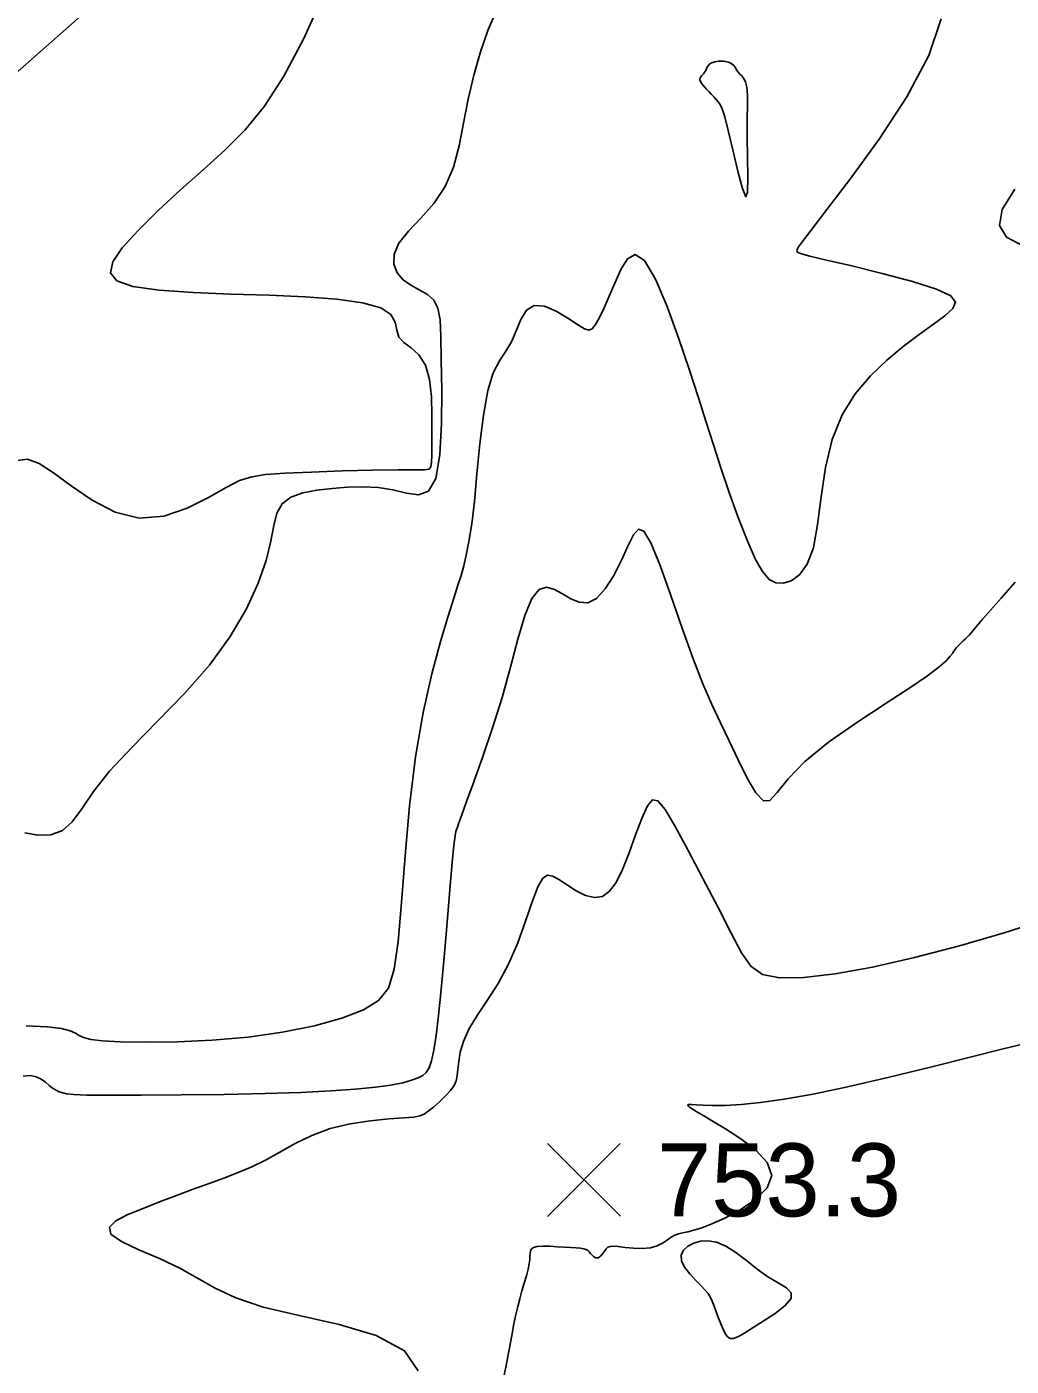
# Model space of a CAD drawing. Extents: x 2566142 to 2571431, y 418755 to 421584.
# Drawn here: x 2568243.6 to 2568445.9, y 420968.6 to 421243.9 of the extents above; entities that cross this region are included whole.
import ezdxf

# ---------------------------------------------------------------- set-up
doc = ezdxf.new("R2010")
doc.units = 0
for name, color, linetype in [('Contour_ADS_Major', 7, 'Continuous'), ('Contour_ADS_Minor', 7, 'Continuous'), ('Contour_ADS_Spot_Elevation', 7, 'Continuous')]:
    doc.layers.add(name, color=color, linetype=linetype)

# ---------------------------------------------------------------- blocks, each defined once
blk = doc.blocks.new('S750')
at = {"layer": 'Contour_ADS_Spot_Elevation'}
for p, q in [((-0.5, 0.498), (0.5, -0.498)), ((-0.498, -0.5), (0.498, 0.5))]:
    blk.add_line(p, q, dxfattribs=at)

msp = doc.modelspace()

# ---------------------------------------------------------------- linework, layer by layer
at = {"layer": 'Contour_ADS_Major'}
msp.add_lwpolyline([(2568243.2, 421078.22), (2568245.83, 421077.73), (2568248.5, 421077.82), (2568250.92, 421078.7), (2568252.94, 421080.51), (2568254.9, 421083.21), (2568257.29, 421086.71), (2568260.61, 421090.95), (2568265.15, 421095.81), (2568270.49, 421101.17), (2568276.04, 421106.85), (2568281.18, 421112.71), (2568285.42, 421118.57), (2568288.73, 421124.25), (2568291.17, 421129.54), (2568292.8, 421134.24), (2568293.75, 421138.2), (2568294.36, 421141.42), (2568295.01, 421143.96), (2568296.09, 421145.87), (2568297.9, 421147.22), (2568300.34, 421148.12), (2568303.21, 421148.68), (2568306.34, 421149.04), (2568309.54, 421149.27), (2568312.73, 421149.35), (2568315.85, 421149.2), (2568318.85, 421148.74), (2568321.64, 421148.05), (2568324.12, 421147.72), (2568326.16, 421148.48), (2568327.64, 421151.09), (2568328.49, 421155.96), (2568328.85, 421162.35), (2568328.89, 421169.2), (2568328.8, 421175.43), (2568328.72, 421180.23), (2568328.54, 421183.67), (2568328.11, 421186.05), (2568327.27, 421187.7), (2568325.94, 421188.89), (2568324.28, 421189.85), (2568322.53, 421190.79), (2568320.94, 421191.91), (2568319.72, 421193.36), (2568319.06, 421195.14), (2568319.12, 421197.19), (2568320.1, 421199.44), (2568322.03, 421201.88), (2568324.58, 421204.56), (2568327.26, 421207.58), (2568329.62, 421211.05), (2568331.29, 421215.02), (2568332.45, 421219.41), (2568333.35, 421224.11), (2568334.29, 421229.01), (2568335.46, 421233.98), (2568336.85, 421238.77), (2568338.37, 421243.13), (2568339.91, 421246.78)], dxfattribs=at)
msp.add_lwpolyline([(2568387.78, 421222.59), (2568388.71, 421218.59), (2568389.73, 421214.24), (2568390.68, 421210.66), (2568391.39, 421208.97), (2568391.75, 421209.94), (2568391.83, 421212.96), (2568391.76, 421217.07), (2568391.68, 421221.31), (2568391.68, 421224.89), (2568391.72, 421227.72), (2568391.72, 421229.9), (2568391.6, 421231.5), (2568391.32, 421232.62), (2568390.93, 421233.37), (2568390.49, 421233.88), (2568390.09, 421234.26), (2568389.77, 421234.63), (2568389.52, 421235), (2568389.31, 421235.34), (2568389.12, 421235.65), (2568388.9, 421235.91), (2568388.66, 421236.14), (2568388.4, 421236.33), (2568388.12, 421236.49), (2568387.82, 421236.62), (2568387.5, 421236.72), (2568387.17, 421236.79), (2568386.83, 421236.84), (2568386.5, 421236.86), (2568386.16, 421236.86), (2568385.8, 421236.83), (2568385.42, 421236.78), (2568385.01, 421236.69), (2568384.6, 421236.57), (2568384.21, 421236.39), (2568383.88, 421236.14), (2568383.61, 421235.82), (2568383.39, 421235.46), (2568383.21, 421235.08), (2568383.04, 421234.74), (2568382.86, 421234.46), (2568382.67, 421234.23), (2568382.48, 421234.02), (2568382.29, 421233.82), (2568382.12, 421233.6), (2568381.99, 421233.34), (2568381.97, 421233.03), (2568382.09, 421232.64), (2568382.38, 421232.17), (2568382.81, 421231.63), (2568383.32, 421231.06), (2568383.85, 421230.5), (2568384.37, 421229.97), (2568384.85, 421229.48), (2568385.3, 421228.99), (2568385.72, 421228.51), (2568386.11, 421227.96), (2568386.53, 421227.03), (2568387.06, 421225.36), (2568387.78, 421222.59)], close=True, dxfattribs=at)
at = {"layer": 'Contour_ADS_Minor'}
for points in [[(2568241.11, 421234.17), (2568248.74, 421240.86), (2568257.58, 421248.71)], [(2568241.71, 421154.76), (2568243.76, 421155.02), (2568246.14, 421154.14), (2568249.07, 421152.24), (2568252.73, 421149.53), (2568257.01, 421146.6), (2568261.73, 421144.17), (2568266.7, 421142.92), (2568271.73, 421143.34), (2568276.57, 421144.98), (2568280.93, 421147.16), (2568284.56, 421149.22), (2568287.35, 421150.63), (2568289.82, 421151.44), (2568292.69, 421151.87), (2568296.64, 421152.13), (2568302.12, 421152.38), (2568308.45, 421152.61), (2568314.68, 421152.79), (2568319.9, 421152.88), (2568323.38, 421152.86), (2568325.35, 421152.85), (2568326.28, 421153.01), (2568326.63, 421153.48), (2568326.79, 421154.41), (2568326.85, 421155.87), (2568326.87, 421157.93), (2568326.88, 421160.68), (2568326.88, 421164.09), (2568326.76, 421167.82), (2568326.36, 421171.4), (2568325.52, 421174.39), (2568324.19, 421176.49), (2568322.6, 421177.91), (2568321.12, 421179), (2568320.07, 421180.13), (2568319.63, 421181.55), (2568319.3, 421183.16), (2568318.44, 421184.76), (2568316.37, 421186.16), (2568312.62, 421187.19), (2568307.33, 421187.9), (2568300.82, 421188.38), (2568293.43, 421188.71), (2568285.52, 421188.97), (2568277.76, 421189.29), (2568270.82, 421189.78), (2568265.42, 421190.55), (2568262.11, 421191.71), (2568260.79, 421193.36), (2568261.25, 421195.58), (2568263.23, 421198.47), (2568266.48, 421202.06), (2568270.61, 421206.12), (2568275.22, 421210.38), (2568279.89, 421214.57), (2568284.3, 421218.55), (2568288.46, 421222.71), (2568292.48, 421227.59), (2568296.46, 421233.72), (2568300.45, 421241.38), (2568304.28, 421249.86)], [(2568396.21, 421130.34), (2568397.58, 421129.62), (2568399.06, 421129.57), (2568400.72, 421130.05), (2568402.42, 421131.25), (2568404, 421133.43), (2568405.28, 421136.85), (2568406.15, 421141.63), (2568406.87, 421147.32), (2568407.75, 421153.35), (2568409.11, 421159.11), (2568411.19, 421164.16), (2568413.88, 421168.48), (2568417, 421172.18), (2568420.36, 421175.39), (2568423.76, 421178.21), (2568427.01, 421180.65), (2568429.94, 421182.75), (2568432.33, 421184.53), (2568433.98, 421186.01), (2568434.51, 421187.32), (2568433.52, 421188.6), (2568430.61, 421189.99), (2568425.63, 421191.57), (2568419.45, 421193.21), (2568413.19, 421194.74), (2568407.95, 421195.97), (2568404.58, 421196.79), (2568402.83, 421197.26), (2568402.14, 421197.49), (2568401.99, 421197.61), (2568401.94, 421197.72), (2568401.91, 421197.86), (2568401.92, 421198.03), (2568402, 421198.27), (2568402.24, 421198.67), (2568403.03, 421199.75), (2568404.83, 421202.11), (2568408.08, 421206.34), (2568413.01, 421212.79), (2568418.83, 421220.82), (2568424.51, 421229.53), (2568429, 421238.03), (2568431.56, 421245.56)], [(2568448.49, 421198.81), (2568444.97, 421200.67), (2568443.52, 421203.09), (2568444.12, 421206.33), (2568446.66, 421210.54)], [(2568243.44, 421038.55), (2568247.77, 421038.35), (2568250.72, 421038), (2568252.51, 421037.57), (2568253.57, 421037.09), (2568254.35, 421036.61), (2568255.28, 421036.18), (2568256.75, 421035.8), (2568259.15, 421035.49), (2568262.86, 421035.28), (2568268.11, 421035.19), (2568274.56, 421035.27), (2568281.71, 421035.61), (2568289.07, 421036.26), (2568296.18, 421037.28), (2568302.7, 421038.61), (2568308.34, 421040.17), (2568312.81, 421041.88), (2568315.92, 421043.78), (2568317.92, 421046.35), (2568319.14, 421050.21), (2568319.94, 421055.94), (2568320.62, 421063.92), (2568321.35, 421073.49), (2568322.26, 421083.76), (2568323.47, 421093.85), (2568325.06, 421102.99), (2568326.85, 421110.93), (2568328.64, 421117.55), (2568330.2, 421122.74), (2568331.38, 421126.47), (2568332.23, 421129.11), (2568332.86, 421131.16), (2568333.4, 421133.09), (2568333.94, 421135.33), (2568334.49, 421138.14), (2568335.04, 421141.73), (2568335.59, 421146.33), (2568336.13, 421151.99), (2568336.72, 421158.16), (2568337.44, 421164.11), (2568338.35, 421169.15), (2568339.49, 421172.75), (2568340.77, 421175.26), (2568342.05, 421177.2), (2568343.22, 421179.13), (2568344.21, 421181.4), (2568345.17, 421183.72), (2568346.32, 421185.63), (2568347.89, 421186.65), (2568350, 421186.49), (2568352.41, 421185.46), (2568354.78, 421184.04), (2568356.8, 421182.69), (2568358.21, 421181.82), (2568359.14, 421181.53), (2568359.83, 421181.81), (2568360.49, 421182.69), (2568361.29, 421184.17), (2568362.25, 421186.15), (2568363.33, 421188.54), (2568364.49, 421191.23), (2568365.72, 421194), (2568367.09, 421196.2), (2568368.68, 421197.08), (2568370.57, 421195.85), (2568372.81, 421192.06), (2568375.23, 421186.38), (2568377.64, 421179.8), (2568379.84, 421173.3), (2568381.68, 421167.64), (2568383.26, 421162.66), (2568384.74, 421157.98), (2568386.28, 421153.23), (2568388, 421148.17), (2568389.82, 421143.08), (2568391.64, 421138.41), (2568393.33, 421134.58), (2568394.83, 421131.92), (2568396.21, 421130.34)], [(2568246.52, 421027.61), (2568247.41, 421026.97), (2568248.19, 421026.32), (2568248.91, 421025.79), (2568249.61, 421025.37), (2568250.28, 421025.04), (2568250.97, 421024.79), (2568251.78, 421024.59), (2568253.22, 421024.44), (2568255.9, 421024.34), (2568260.41, 421024.3), (2568267.12, 421024.31), (2568275.33, 421024.38), (2568284.14, 421024.5), (2568292.59, 421024.68), (2568299.94, 421024.91), (2568306.11, 421025.2), (2568311.19, 421025.54), (2568315.27, 421025.95), (2568318.45, 421026.4), (2568320.88, 421026.89), (2568322.68, 421027.39), (2568324.01, 421027.88), (2568324.99, 421028.36), (2568325.72, 421028.99), (2568326.28, 421029.94), (2568326.76, 421031.4), (2568327.24, 421033.55), (2568327.73, 421036.57), (2568328.24, 421040.67), (2568328.8, 421046.03), (2568329.39, 421052.66), (2568329.98, 421059.83), (2568330.54, 421066.63), (2568331.01, 421072.15), (2568331.36, 421075.71), (2568331.62, 421077.66), (2568331.8, 421078.54), (2568331.95, 421078.95), (2568332.12, 421079.4), (2568332.42, 421080.28), (2568333, 421081.92), (2568334, 421084.67), (2568335.5, 421088.75), (2568337.35, 421093.91), (2568339.34, 421099.79), (2568341.28, 421106.03), (2568343, 421112.26), (2568344.54, 421118.03), (2568345.98, 421122.9), (2568347.41, 421126.41), (2568348.9, 421128.25), (2568350.45, 421128.73), (2568352.05, 421128.28), (2568353.71, 421127.35), (2568355.41, 421126.35), (2568357.15, 421125.63), (2568358.92, 421125.53), (2568360.71, 421126.38), (2568362.5, 421128.37), (2568364.23, 421131.15), (2568365.81, 421134.25), (2568367.17, 421137.19), (2568368.29, 421139.47), (2568369.3, 421140.65), (2568370.43, 421140.27), (2568371.88, 421137.86), (2568373.77, 421133.21), (2568375.99, 421127.04), (2568378.32, 421120.31), (2568380.58, 421114), (2568382.59, 421108.84), (2568384.43, 421104.6), (2568386.18, 421100.86), (2568387.95, 421097.16), (2568389.81, 421093.23), (2568391.67, 421089.47), (2568393.44, 421086.47), (2568395, 421084.81), (2568396.34, 421084.9), (2568397.87, 421086.53), (2568400.09, 421089.32), (2568403.51, 421092.88), (2568408.42, 421096.85), (2568414.22, 421100.9), (2568420.06, 421104.73), (2568425.12, 421108.02), (2568428.76, 421110.53), (2568431.13, 421112.35), (2568432.55, 421113.62), (2568433.36, 421114.49), (2568433.85, 421115.12), (2568434.17, 421115.58), (2568434.42, 421115.96), (2568434.7, 421116.33), (2568435.1, 421116.75), (2568435.58, 421117.21), (2568436.09, 421117.68), (2568436.56, 421118.12), (2568436.96, 421118.52), (2568437.34, 421118.94)], [(2568437.34, 421118.94), (2568437.77, 421119.44), (2568438.32, 421120.09), (2568439.07, 421120.97), (2568440.14, 421122.22), (2568441.69, 421124), (2568443.85, 421126.47), (2568446.74, 421129.76)], [(2568286.56, 420982.66), (2568282.3, 420984.67), (2568278.7, 420986.75), (2568275.05, 420988.79), (2568270.87, 420990.73), (2568266.64, 420992.54), (2568263.07, 420994.23), (2568260.88, 420995.77), (2568260.59, 420997.19), (2568261.92, 420998.51), (2568264.39, 420999.79), (2568267.52, 421001.07), (2568270.9, 421002.38), (2568274.36, 421003.7), (2568277.78, 421004.98), (2568281.06, 421006.19), (2568284.12, 421007.3), (2568287.01, 421008.41), (2568289.84, 421009.61), (2568292.68, 421011), (2568295.64, 421012.64), (2568298.79, 421014.39), (2568302.21, 421016.05), (2568305.97, 421017.45), (2568310.09, 421018.44), (2568314.24, 421019.07), (2568318.03, 421019.44), (2568321.08, 421019.67), (2568323.12, 421019.84), (2568324.39, 421020.06), (2568325.26, 421020.41), (2568326.1, 421021.01), (2568327.19, 421021.89), (2568328.44, 421022.99), (2568329.67, 421024.16), (2568330.71, 421025.3), (2568331.41, 421026.31), (2568331.82, 421027.29), (2568332.06, 421028.35), (2568332.2, 421029.63), (2568332.37, 421031.23), (2568332.7, 421033.16), (2568333.36, 421035.38), (2568334.48, 421037.89), (2568336.17, 421040.67), (2568338.25, 421043.78), (2568340.49, 421047.27), (2568342.64, 421051.23), (2568344.51, 421055.63), (2568346.11, 421060.06), (2568347.46, 421064.06), (2568348.63, 421067.13), (2568349.65, 421068.92), (2568350.65, 421069.57), (2568351.75, 421069.36), (2568353.07, 421068.57), (2568354.71, 421067.46), (2568356.55, 421066.31), (2568358.45, 421065.38), (2568360.27, 421064.93), (2568361.9, 421065.19), (2568363.36, 421066.23), (2568364.72, 421068.06), (2568366.05, 421070.72), (2568367.4, 421074.12), (2568368.73, 421077.81), (2568369.99, 421081.21), (2568371.15, 421083.78), (2568372.21, 421085.03), (2568373.34, 421084.81), (2568374.8, 421083.04), (2568376.81, 421079.66), (2568379.5, 421074.73), (2568382.59, 421068.89), (2568385.69, 421062.93), (2568388.4, 421057.62), (2568390.5, 421053.58), (2568392.43, 421050.82), (2568394.82, 421049.15), (2568398.29, 421048.42), (2568403.3, 421048.48), (2568409.76, 421049.24), (2568417.42, 421050.64), (2568426.04, 421052.6), (2568435.29, 421055.03), (2568444.49, 421057.69), (2568452.86, 421060.33)], [(2568379.82, 421022.41), (2568380.32, 421022.4), (2568381.21, 421022.35), (2568382.61, 421022.26), (2568384.57, 421022.2), (2568387.16, 421022.22), (2568390.41, 421022.4), (2568394.41, 421022.81), (2568399.29, 421023.5), (2568405.21, 421024.55), (2568412.33, 421026.03), (2568420.62, 421027.95), (2568429.34, 421030.08), (2568437.54, 421032.14), (2568444.29, 421033.84), (2568448.9, 421034.98)], [(2568242.83, 421028.2), (2568244.26, 421028.34), (2568245.49, 421028.11), (2568246.52, 421027.61)], [(2568341.48, 420965.47), (2568342.16, 420968.79), (2568342.77, 420972.04), (2568343.29, 420974.95), (2568343.73, 420977.32), (2568344.12, 420979.25), (2568344.5, 420980.92), (2568344.92, 420982.49), (2568345.38, 420984.1), (2568345.86, 420985.71), (2568346.31, 420987.22), (2568346.65, 420988.55), (2568346.87, 420989.64), (2568346.98, 420990.52), (2568347.03, 420991.22), (2568347.06, 420991.81), (2568347.13, 420992.31), (2568347.33, 420992.72), (2568347.76, 420993.04), (2568348.52, 420993.23), (2568349.67, 420993.3), (2568351.1, 420993.27), (2568352.63, 420993.19), (2568354.12, 420993.1), (2568355.41, 420993.02), (2568356.5, 420992.95), (2568357.39, 420992.86), (2568358.07, 420992.75), (2568358.56, 420992.59), (2568358.92, 420992.39), (2568359.2, 420992.12), (2568359.48, 420991.8), (2568359.8, 420991.43), (2568360.18, 420991.09), (2568360.58, 420990.88), (2568361.02, 420990.9), (2568361.46, 420991.2), (2568361.9, 420991.69), (2568362.33, 420992.25), (2568362.71, 420992.75), (2568363.06, 420993.09), (2568363.48, 420993.26), (2568364.13, 420993.3), (2568365.13, 420993.22), (2568366.57, 420993.05), (2568368.29, 420992.89), (2568370.1, 420992.83), (2568371.78, 420992.97), (2568373.17, 420993.37), (2568374.3, 420993.94), (2568375.24, 420994.56), (2568376.05, 420995.12), (2568376.81, 420995.53), (2568377.58, 420995.81), (2568378.45, 420996.03), (2568379.47, 420996.26), (2568380.74, 420996.57), (2568382.35, 420997.06), (2568384.42, 420997.86), (2568387.05, 420999.06), (2568390.22, 421000.76), (2568393.36, 421002.87), (2568395.77, 421005.27), (2568396.74, 421007.84), (2568395.8, 421010.48), (2568393.44, 421013.03), (2568390.35, 421015.38), (2568387.23, 421017.38), (2568384.68, 421018.94), (2568382.74, 421020.1), (2568381.33, 421020.92), (2568380.38, 421021.49), (2568379.82, 421021.88), (2568379.54, 421022.12), (2568379.47, 421022.26), (2568379.5, 421022.34), (2568379.59, 421022.39), (2568379.82, 421022.41)], [(2568324.03, 420967.66), (2568321.24, 420971.79), (2568315.44, 420974.91), (2568307.8, 420977.22), (2568299.61, 420979.06), (2568292.2, 420980.78), (2568286.56, 420982.66)]]:
    msp.add_lwpolyline(points, dxfattribs=at)
msp.add_lwpolyline([(2568382.24, 420985.15), (2568383.06, 420984.27), (2568383.64, 420983.55), (2568384.07, 420982.85), (2568384.45, 420982.02), (2568384.87, 420980.98), (2568385.32, 420979.78), (2568385.79, 420978.52), (2568386.26, 420977.31), (2568386.71, 420976.23), (2568387.17, 420975.34), (2568387.65, 420974.69), (2568388.2, 420974.34), (2568388.85, 420974.33), (2568389.72, 420974.68), (2568390.96, 420975.38), (2568392.7, 420976.45), (2568394.98, 420977.86), (2568397.41, 420979.47), (2568399.49, 420981.09), (2568400.73, 420982.55), (2568400.75, 420983.72), (2568399.75, 420984.73), (2568398.04, 420985.77), (2568395.94, 420987.02), (2568393.73, 420988.6), (2568391.51, 420990.34), (2568389.34, 420991.99), (2568387.28, 420993.3), (2568385.38, 420994.09), (2568383.65, 420994.39), (2568382.09, 420994.3), (2568380.7, 420993.9), (2568379.5, 420993.28), (2568378.6, 420992.46), (2568378.11, 420991.45), (2568378.16, 420990.27), (2568378.82, 420988.95), (2568379.89, 420987.58), (2568381.11, 420986.27), (2568382.24, 420985.15)], close=True, dxfattribs=at)

# ---------------------------------------------------------------- block references
at = {"layer": 'Contour_ADS_Spot_Elevation', "xscale": 15, "yscale": 15}
msp.add_blockref('S750', (2568358.12, 421006.92), dxfattribs=at)

# ---------------------------------------------------------------- texts
at = {"layer": 'Contour_ADS_Spot_Elevation'}
msp.add_text('753.3', height=15, dxfattribs=at).set_placement((2568373.12, 420999.42))

doc.saveas('drawing.dxf')
